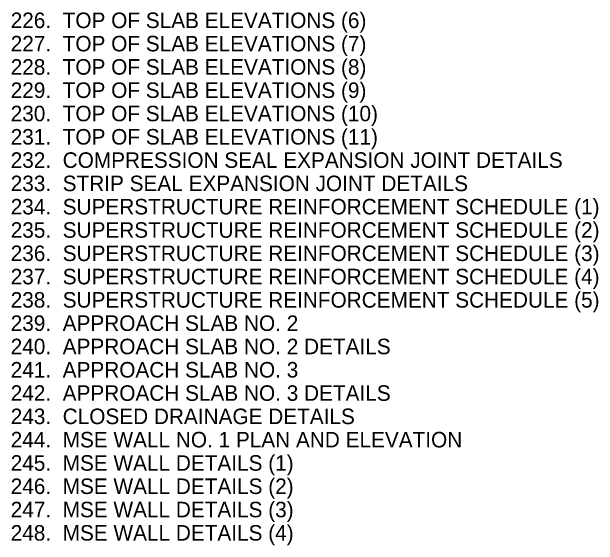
# Model space of a CAD drawing. Extents: x -125.5 to -89.4, y -5.1 to 16.9.
# Drawn here: x -103.606 to -98.888, y 1.715 to 6.009 of the extents above; entities that cross this region are included whole.
import ezdxf

# ---------------------------------------------------------------- set-up
doc = ezdxf.new("R2010")
doc.units = 0
doc.layers.add('BR_TEXT', color=7, linetype='Continuous')

msp = doc.modelspace()

# ---------------------------------------------------------------- texts
at = {"layer": 'BR_TEXT'}
for s, p in [('226.  TOP OF SLAB ELEVATIONS (6)', (-103.6141, 5.8777)), ('227.  TOP OF SLAB ELEVATIONS (7)', (-103.6141, 5.6902)), ('228.  TOP OF SLAB ELEVATIONS (8)', (-103.6141, 5.5027)), ('229.  TOP OF SLAB ELEVATIONS (9)', (-103.6141, 5.3152)), ('230.  TOP OF SLAB ELEVATIONS (10)', (-103.6141, 5.1277)), ('231.  TOP OF SLAB ELEVATIONS (11)', (-103.6141, 4.9402)), ('232.  COMPRESSION SEAL EXPANSION JOINT DETAILS', (-103.6141, 4.7527)), ('233.  STRIP SEAL EXPANSION JOINT DETAILS', (-103.6141, 4.5652)), ('234.  SUPERSTRUCTURE REINFORCEMENT SCHEDULE (1)', (-103.6141, 4.3777)), ('235.  SUPERSTRUCTURE REINFORCEMENT SCHEDULE (2)', (-103.6141, 4.1902)), ('236.  SUPERSTRUCTURE REINFORCEMENT SCHEDULE (3)', (-103.6141, 4.0027)), ('237.  SUPERSTRUCTURE REINFORCEMENT SCHEDULE (4)', (-103.6141, 3.8152)), ('238.  SUPERSTRUCTURE REINFORCEMENT SCHEDULE (5)', (-103.6141, 3.6277)), ('239.  APPROACH SLAB NO. 2', (-103.6141, 3.4402)), ('240.  APPROACH SLAB NO. 2 DETAILS', (-103.6141, 3.2527)), ('241.  APPROACH SLAB NO. 3', (-103.6141, 3.0652)), ('242.  APPROACH SLAB NO. 3 DETAILS', (-103.6141, 2.8777)), ('243.  CLOSED DRAINAGE DETAILS', (-103.6141, 2.6902)), ('244.  MSE WALL NO. 1 PLAN AND ELEVATION', (-103.6141, 2.5027)), ('245.  MSE WALL DETAILS (1)', (-103.6141, 2.3152)), ('246.  MSE WALL DETAILS (2)', (-103.6141, 2.1277)), ('247.  MSE WALL DETAILS (3)', (-103.6141, 1.9402)), ('248.  MSE WALL DETAILS (4)', (-103.6141, 1.7527))]:
    msp.add_text(s, height=0.125, dxfattribs=at).set_placement(p)

doc.saveas('drawing.dxf')
